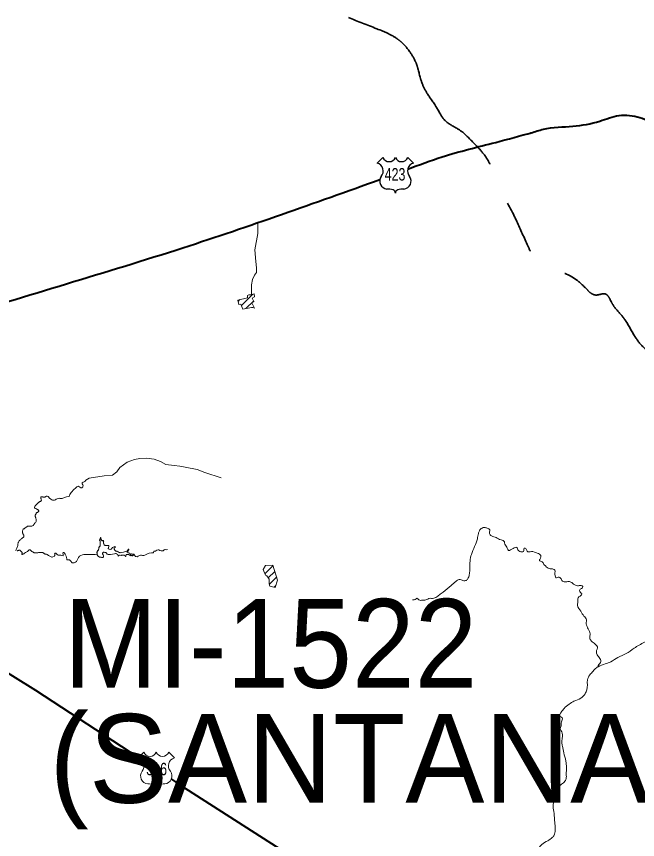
# Model space of a CAD drawing. Extents: x -1643653 to 4543381, y 1624270 to 13878484.
# Drawn here: x 598511 to 602011, y 8914352 to 8918990 of the extents above; entities that cross this region are included whole.
import ezdxf
from ezdxf.enums import TextEntityAlignment as Align

# ---------------------------------------------------------------- set-up
doc = ezdxf.new("R2010")
doc.units = 0
doc.header["$LTSCALE"] = 200
doc.linetypes.add('LONG_DASH_SHORT_DASH', pattern=[9.9, 6, -1.2, 1.5, -1.2])
doc.layers.add('6', color=7, linetype='Continuous', lineweight=13)
doc.layers.add('60', color=7, linetype='Continuous', lineweight=13)

msp = doc.modelspace()

# ---------------------------------------------------------------- linework, layer by layer
at = {"layer": '6', "lineweight": 25}
for p, q in [((600544.7, 8918164.1), (600576.6, 8918196.1)), ((600716.5, 8918196.1), (600748.5, 8918164.1))]:
    msp.add_line(p, q, dxfattribs=at)
at = {"layer": '6'}
for p, q in [((599779.1, 8917360.8), (599843, 8917424.7)), ((599760.1, 8917384.1), (599770.4, 8917394.5)), ((599804.6, 8917343.8), (599848.1, 8917387.3)), ((599850.7, 8917347.5), (599851.7, 8917348.5)), ((599911.6, 8915849.7), (599957.3, 8915895.4)), ((599930.4, 8915826.1), (599967.3, 8915863)), ((599936, 8915789.3), (599977.2, 8915830.5)), ((599963, 8915773.8), (599972, 8915782.8)), ((599197.4, 8914812), (599229.4, 8914844)), ((599369.2, 8914844), (599401.2, 8914812))]:
    msp.add_line(p, q, dxfattribs=at)
for points in [[(599871, 8917832.6), (599871.8, 8917767.7), (599854.5, 8917674.6), (599859.5, 8917608.7), (599864.6, 8917573), (599864.4, 8917548.3), (599853.3, 8917532), (599842.1, 8917507.4), (599836.4, 8917477.3), (599835.9, 8917422.3)], [(599664, 8916389.5), (599573.3, 8916420.2), (599530.2, 8916437.2), (599461.5, 8916451.1), (599431.6, 8916456.9), (599399.5, 8916459.4), (599354, 8916466.4), (599323.1, 8916483.3), (599287.7, 8916495.8), (599244.5, 8916500.6), (599205.7, 8916498.8), (599176.8, 8916494.6), (599135.6, 8916479.4), (599094.3, 8916448.7), (599077.5, 8916423.3), (599051.8, 8916404.7), (599005.2, 8916401.8), (598921.8, 8916388.1), (598911.5, 8916383.7), (598902.3, 8916377.5), (598896.6, 8916370.4)], [(598896.6, 8916370.4), (598896.5, 8916370.3), (598893.5, 8916368.7), (598887.3, 8916366.8), (598882.2, 8916362.8), (598880.8, 8916359.9), (598881.9, 8916356.9), (598884.8, 8916351.1), (598886.9, 8916345), (598886.3, 8916341.8), (598884.8, 8916338.9), (598880.1, 8916334.3), (598877, 8916333.6), (598873.8, 8916334.3), (598868.3, 8916337.8), (598863.6, 8916342.2), (598860.4, 8916342.9), (598857.1, 8916342.3), (598851.2, 8916339.6), (598846.8, 8916334.9), (598841.8, 8916330.9), (598836.5, 8916327.1), (598819.4, 8916307.3), (598815.4, 8916302.1), (598813, 8916296.2), (598811.1, 8916289.8), (598809.4, 8916287.1), (598806.8, 8916285.3), (598793.8, 8916283.8), (598781.7, 8916278.8), (598769.7, 8916273.6), (598763.3, 8916273), (598756.9, 8916274.3)], [(598756.7, 8916274.4), (598751.2, 8916275.1), (598746, 8916273.7), (598736, 8916269.2), (598731.6, 8916266.1), (598726.3, 8916264.3), (598720.8, 8916264.1), (598715.4, 8916265), (598710.1, 8916266.6), (598705.4, 8916269.2), (598697.1, 8916276.4), (598689.5, 8916284.3), (598684.8, 8916287.2), (598682.1, 8916287.3), (598679.5, 8916286.3)], [(599008.9, 8915970.5), (599005.2, 8915971.1), (599001.8, 8915970.8), (598999, 8915968.7), (598996.6, 8915966.3), (598996.6, 8915962.6), (598998.2, 8915958.4), (599000.3, 8915955.5), (599001.3, 8915951.8), (599001.6, 8915948.2), (599001.1, 8915944.2), (599000.3, 8915942.6), (598996.1, 8915942.1), (598992.9, 8915942.1), (598988.2, 8915942.4), (598980.2, 8915944.2), (598973.4, 8915946.6), (598969.4, 8915950.7), (598967.1, 8915956.6), (598965.2, 8915970.8), (598965.5, 8915975.2), (598968.9, 8915978.4), (598971.6, 8915982.3), (598974.5, 8915987), (598975.3, 8915992.3), (598975.3, 8915995.2), (598975.5, 8915998.1), (598976.8, 8916000.4), (598980.5, 8916004.1), (598983.4, 8916008.3), (598983.4, 8916013.8), (598983.2, 8916023.6), (598982.9, 8916029.1), (598982.9, 8916032.5), (598981.6, 8916036.2), (598979, 8916039.9), (598981.8, 8916043.3), (598983.7, 8916049.1), (598985.3, 8916051.4), (598985.5, 8916054.1), (598987.1, 8916053.5), (598987.4, 8916050.1), (598987.7, 8916046.6), (598989.2, 8916043.5), (598993.2, 8916037), (598994.2, 8916034.6), (598996.6, 8916034.9), (598999, 8916036.4), (599001.1, 8916036.7), (599002.9, 8916034.1), (599001.3, 8916030.1), (599001.6, 8916025.9), (599001.6, 8916022), (599003.2, 8916017.2), (599005.3, 8916012.8), (599008.7, 8916010.4), (599011.8, 8916009.8)], [(599084.8, 8915949.4), (599084.9, 8915951), (599083.9, 8915953.7), (599079.6, 8915958), (599076.2, 8915963), (599073.6, 8915964.1), (599070.4, 8915964.2), (599064.2, 8915963), (599040.7, 8915959.1), (599028.6, 8915958.6), (599023.2, 8915961.1), (599019.1, 8915965.5), (599014.9, 8915969.5), (599008.8, 8915970.5), (599002.7, 8915971), (598997.7, 8915967.7), (598996.3, 8915965.3), (598996.7, 8915962.2), (598999.3, 8915956.9), (599001.4, 8915951.3), (599001.3, 8915945.3), (599000.2, 8915942.6), (598997.3, 8915942), (598991.2, 8915942.1), (598979.4, 8915944.4), (598973.7, 8915946.4), (598969.8, 8915950.1), (598967.4, 8915955.4), (598966.2, 8915961.8), (598965.5, 8915968.6), (598965.3, 8915974.9), (598969.6, 8915979.1), (598972.8, 8915984.2), (598975.1, 8915989.6), (598975.3, 8915995.6), (598975.7, 8915998.6), (598977.4, 8916001.1), (598981.7, 8916005.3), (598983.3, 8916007.9), (598983.7, 8916010.8), (598983.3, 8916016.9), (598982.9, 8916028.8), (598982.4, 8916034.8), (598978.9, 8916039.8), (598982.5, 8916044.6), (598983.1, 8916047.6), (598984.6, 8916050.1), (598985.2, 8916053.2), (598985.8, 8916054.1), (598987.3, 8916053.4), (598987.5, 8916047.2), (598993.2, 8916036.7), (598993.7, 8916035.1), (598994.8, 8916034.4), (598997.7, 8916035.6), (599000.4, 8916036.8), (599002.7, 8916035), (599002.3, 8916032.1), (599001.2, 8916029.3), (599001.6, 8916023.2), (599003.1, 8916017.5), (599005.8, 8916012.2), (599008.3, 8916010.6), (599011.3, 8916009.8), (599017.3, 8916009.3), (599029.2, 8916008.2), (599032, 8916006.7), (599032.1, 8916004), (599029.5, 8915998.4), (599028.7, 8915992.5), (599030.6, 8915990.1), (599033.2, 8915988.5), (599038.9, 8915986.9), (599045, 8915987.8), (599047.6, 8915989.5), (599049, 8915992.2), (599049.9, 8915995.1), (599052.1, 8915996.9), (599057.1, 8916000.2), (599062.8, 8916002.2), (599065.4, 8916003.5), (599068.2, 8916003.6), (599068.2, 8916000.4), (599067.4, 8915997.6), (599062.5, 8915994.1), (599062.3, 8915988.1), (599065, 8915982.7), (599069.2, 8915978.6), (599071.7, 8915976.9), (599074.9, 8915976.9), (599077.9, 8915976.9), (599079.8, 8915974.8), (599082.2, 8915973.6), (599085.4, 8915973.6), (599090.5, 8915970.2), (599093, 8915968.8)], [(599093, 8915968.8), (599096, 8915968.4), (599102, 8915968.8), (599113.8, 8915971.1), (599125.2, 8915974.7), (599130.8, 8915973.1), (599134.3, 8915973.4), (599135.2, 8915974), (599134.6, 8915975.3), (599134.3, 8915978.3), (599136.3, 8915980.6), (599138.7, 8915982.3), (599141.3, 8915983.6), (599141.8, 8915985), (599141.2, 8915986.4), (599141.1, 8915987.6), (599142.8, 8915987.7), (599144.3, 8915986.8), (599144.6, 8915985.5), (599142.6, 8915983.1), (599139.9, 8915977.8), (599139.2, 8915971.8), (599139.2, 8915968.8), (599141.3, 8915967), (599147.4, 8915966.3), (599150.5, 8915965.1), (599152.7, 8915963), (599152.8, 8915960), (599154.1, 8915959.1), (599155.8, 8915959.1), (599157.2, 8915961.6), (599159.7, 8915962.2), (599166.6, 8915960.2), (599172.6, 8915960.3), (599175.4, 8915959.6), (599177.1, 8915956.7), (599177, 8915955.3), (599175.6, 8915955.1), (599173.2, 8915956.8), (599167.2, 8915957.4), (599167, 8915955.9), (599168.3, 8915955.1), (599168.7, 8915953.8), (599167.5, 8915952.9), (599165.6, 8915950.8), (599162.7, 8915951.6), (599160.7, 8915953.8), (599159.3, 8915953.6), (599158.3, 8915952.4), (599155.8, 8915950.9), (599153.3, 8915952.5), (599147.8, 8915954.7), (599143.4, 8915958.7), (599137.4, 8915959.2), (599134.3, 8915959.1), (599132, 8915957.4), (599129.5, 8915955.8), (599127.7, 8915953.4), (599127.5, 8915947.2), (599127.1, 8915946.7), (599126.1, 8915947.5), (599123.5, 8915950.7), (599118.3, 8915953.7), (599112.6, 8915955.2), (599106.6, 8915954.9), (599103.8, 8915953.7), (599100.8, 8915953.5), (599094.9, 8915954.2), (599091.9, 8915954.2), (599089.1, 8915953.3), (599087.7, 8915950.6), (599084.9, 8915949.5)], [(599176.8, 8915955.2), (599177.7, 8915952.1), (599179.8, 8915949.5), (599182.3, 8915947.3), (599185.3, 8915946.2), (599191.9, 8915945.7), (599197.9, 8915948.5), (599209.9, 8915953.8), (599212.9, 8915955.1), (599216.1, 8915954.6), (599222.5, 8915953.2), (599228.9, 8915952.1), (599235.1, 8915954.3), (599246.6, 8915960.7), (599258.6, 8915965.9), (599271.5, 8915967.2), (599278, 8915967.5), (599281.5, 8915967.6), (599284.1, 8915969.1), (599286.3, 8915975.3), (599288.3, 8915977.7), (599291.6, 8915977.5), (599294.8, 8915977.3), (599297.7, 8915979), (599303, 8915982.6), (599309.2, 8915984.8), (599312.6, 8915985.5), (599315.2, 8915983.9), (599317.7, 8915981.7), (599320.7, 8915980.5), (599327.2, 8915979.6), (599333.7, 8915979.2), (599336.9, 8915978.5), (599338.4, 8915979), (599339.3, 8915980.4), (599343.9, 8915985), (599346.9, 8915986.2), (599350.2, 8915986.3), (599356.7, 8915984.8), (599363.2, 8915985.6)], [(598679.3, 8915960.3), (598680.9, 8915959.6), (598684.7, 8915957.5), (598691.2, 8915953.3), (598703.5, 8915946.7), (598710, 8915943.5), (598713.4, 8915943.1), (598716.8, 8915944.3), (598723, 8915947.6), (598725.8, 8915949.9), (598727.3, 8915953), (598727.4, 8915960.1), (598726.6, 8915963.4), (598727.6, 8915964.8), (598729.4, 8915965.5), (598732.8, 8915965.5), (598736.1, 8915964.1), (598741.1, 8915959.1), (598743.6, 8915956.6), (598746.7, 8915954.8), (598753.7, 8915954.9), (598760.8, 8915955.2), (598767.5, 8915952.9), (598774, 8915950.1), (598775.1, 8915951.3), (598775, 8915953.1), (598775.4, 8915956.6), (598774.8, 8915960), (598773.3, 8915963.2), (598773.3, 8915966.7), (598776, 8915969), (598779.5, 8915968.9), (598782, 8915966.5), (598785.6, 8915960.4), (598792.2, 8915948), (598795, 8915934.1), (598795.2, 8915930.6), (598796.7, 8915927.7), (598800.2, 8915927.6), (598804.3, 8915928.3), (598807.8, 8915928.6), (598811, 8915927.6), (598816.6, 8915923.1), (598824.8, 8915912), (598825.9, 8915911.7)]]:
    msp.add_lwpolyline(points, dxfattribs=at)
for points in [[(599850.5, 8917427.2), (599834.3, 8917421.8), (599821.6, 8917421.3), (599813.8, 8917417.5), (599813.2, 8917405.3), (599758.2, 8917391.4), (599764.6, 8917366.4), (599775.7, 8917369.7), (599787.1, 8917340.2), (599836, 8917350.3), (599843.2, 8917350.2), (599852.5, 8917346.8), (599837.8, 8917375.8), (599849.5, 8917384.5), (599839.7, 8917403.4), (599853.1, 8917410)], [(599968.6, 8915772.5), (599982.2, 8915814.2), (599956.8, 8915897.3), (599915.6, 8915895.7), (599902.2, 8915874.7), (599914.8, 8915841.3), (599922.6, 8915837.8), (599935.3, 8915818.7), (599934.5, 8915793.9), (599939.4, 8915779.5)]]:
    msp.add_lwpolyline(points, close=True, dxfattribs=at)
at = {"layer": '6', "lineweight": 40}
for points in [[(596588.2, 8916457.2), (598619.5, 8915193.9), (599198.7, 8914813.4)], [(599384.5, 8914691.3), (599431.6, 8914660.4), (600961.1, 8913682.3), (601460.1, 8913331.7), (601690.5, 8912983.4), (601771, 8912890.8), (601830.7, 8912847.9), (601883.5, 8912819.1), (601916.8, 8912809.3)]]:
    msp.add_lwpolyline(points, dxfattribs=at)
at = {"layer": '6', "lineweight": 25}
for centre, radius, start, end in [((600611.6, 8918209.5), 37.4, 200.9593, 339.0407), ((600681.5, 8918209.5), 37.4, 200.9593, 339.0407), ((600532.2, 8918119.7), 46.1, 317.5721, 74.3689), ((600760.9, 8918119.7), 46.1, 105.6277, 222.4279), ((600602.9, 8918062.7), 44.9, 144.7373, 264.6578), ((600690.2, 8918062.7), 44.9, 275.3422, 35.2627), ((600598.5, 8917900), 118, 72.8937, 89.9006), ((600627.7, 8917994.7), 18.9, 357.6934, 72.9296), ((600665.4, 8917994.7), 18.9, 107.0704, 182.3065), ((600694.6, 8917900), 118, 90.0994, 107.1063)]:
    msp.add_arc(centre, radius, start, end, dxfattribs=at)
at = {"layer": '6'}
for centre, radius, start, end in [((599264.3, 8914857.4), 37.4, 200.9593, 339.0407), ((599334.3, 8914857.4), 37.4, 200.9593, 339.0407), ((599185, 8914767.6), 46.1, 317.5721, 74.3689), ((599413.6, 8914767.6), 46.1, 105.6277, 222.4279), ((599255.7, 8914710.6), 44.9, 144.7373, 264.6578), ((599342.9, 8914710.6), 44.9, 275.3422, 35.2627), ((599251.3, 8914547.9), 118, 72.8937, 89.9006), ((599280.4, 8914642.6), 18.9, 357.6934, 72.9296), ((599318.2, 8914642.6), 18.9, 107.0704, 182.3065), ((599347.3, 8914547.9), 118, 90.0994, 107.1063)]:
    msp.add_arc(centre, radius, start, end, dxfattribs=at)
for points in [[(598300.5, 8917392.3), (598315.3, 8917441.1), (598255.3, 8917504.1), (598239.6, 8917592.4), (598271.1, 8917724.9), (598331, 8917860.5), (598362.6, 8917945.7), (598337.3, 8918008.8), (598271.1, 8918059.2), (598264.8, 8918122.3), (598283.7, 8918169.6), (598293.2, 8918216.9), (598258.5, 8918251.6), (598220.6, 8918330.5), (598230.1, 8918494.5), (598230.1, 8918586), (598223.8, 8918652.2), (598198.6, 8918705.8), (598223.8, 8918775.2), (598277.4, 8918895.6), (598337.3, 8919006), (598365.7, 8919135.4), (598368.9, 8919223.8), (598359.4, 8919260.4), (598397.3, 8919298.2), (598463.5, 8919374), (598532.9, 8919493.9), (598564.4, 8919569.6), (598630.7, 8919607.5), (598678, 8919639.1), (598668.5, 8919676.9), (598715.8, 8919736.9), (598775.8, 8919809.5), (598854.6, 8919853.7), (598920.8, 8919907.3)], [(601609.2, 8914720.1), (601610.4, 8914757.2), (601607.5, 8914794.4), (601595.3, 8914840.8), (601588.3, 8914877.4), (601584.2, 8914897.8), (601587.2, 8914923.4), (601583.7, 8914959.4), (601575.5, 8914976.8), (601580.2, 8914990.7), (601580.2, 8915008.2), (601585.4, 8915021.5), (601583.1, 8915041.8), (601574.4, 8915045.9), (601573.2, 8915055.8), (601581.3, 8915069.7), (601597.6, 8915091.2), (601625.5, 8915115), (601652.7, 8915131.2), (601691.6, 8915149.2), (601715.4, 8915173), (601725.8, 8915195.1), (601729.3, 8915251.6), (601734, 8915267.3), (601750.8, 8915290.5), (601770.5, 8915312), (601789.1, 8915326), (601829.1, 8915341.6), (601860.5, 8915353.8), (601900.5, 8915378.2), (601947.5, 8915399.7), (601991.6, 8915429.9), (602050.8, 8915463.6), (602115.8, 8915492.6), (602158.7, 8915505.4), (602314.3, 8915536.7), (602476.2, 8915677.8), (602669.4, 8915813.7), (602862.7, 8915954.7), (603014.1, 8916106.3), (603097.7, 8916148.1), (603186.5, 8916137.6), (603238.7, 8916163.8), (603270, 8916247.4), (603290.9, 8916378), (603348.4, 8916461.6), (603437.2, 8916492.9), (603499.8, 8916524.3), (603536.4, 8916555.7), (603567.7, 8916691.5), (603620, 8916775.1), (603620, 8916874.4), (603661.7, 8916952.8), (603729.6, 8917041.6), (603828.9, 8917146.1)], [(600743.3, 8915702.8), (600758.9, 8915705), (600766.6, 8915711.7), (600778.8, 8915702.8), (600799.9, 8915700.6), (600823.2, 8915703.9), (600834.4, 8915710.6), (600849.9, 8915710.6), (600875.4, 8915716.1), (600894.3, 8915730.6), (600915.4, 8915746.1), (600960.9, 8915783.8), (600986.5, 8915806), (601006.4, 8915817.1), (601027.5, 8915811.6), (601046.4, 8915812.7), (601057.5, 8915826), (601064.2, 8915850.4), (601066.4, 8915878.2), (601067.5, 8915921.5), (601075.3, 8915959.2), (601093, 8916003.7), (601108.6, 8916045.8), (601114.1, 8916076.9), (601119.7, 8916092.5), (601135.2, 8916106.9), (601148.5, 8916111.3), (601164.1, 8916105.8), (601178.5, 8916096.9), (601176.3, 8916075.8), (601188.5, 8916063.6), (601214, 8916053.6), (601241.8, 8916040.3), (601260.7, 8916030.3), (601262.9, 8916015.9), (601270.7, 8916004.8), (601277.3, 8915993.7), (601284, 8915981.4), (601295.1, 8915983.7), (601310.6, 8915992.6), (601330.6, 8915998.1), (601337.3, 8915983.7), (601348.4, 8915975.9), (601368.4, 8915975.9), (601372.8, 8915993.7), (601381.7, 8915992.6), (601388.3, 8915977), (601412.8, 8915974.8), (601446.1, 8915965.9), (601466.1, 8915952.6), (601463.8, 8915938.2), (601458.3, 8915924.8), (601473.8, 8915917.1), (601483.8, 8915902.6), (601497.1, 8915889.3)], [(598825.9, 8915911.7), (598844.6, 8915914.6), (598861.2, 8915942.1), (598891.6, 8915957.8), (598918, 8915957.8), (598966.1, 8915959.7)], [(601497.1, 8915889.3), (601518.2, 8915877.1), (601536, 8915876), (601544.9, 8915870.4), (601544.9, 8915851.6), (601547.1, 8915839.3), (601551.5, 8915826), (601569.3, 8915830.5), (601577.1, 8915824.9), (601588.2, 8915808.3), (601608.2, 8915803.8), (601628.2, 8915806), (601643.7, 8915797.2), (601672.6, 8915781.6), (601693.7, 8915783.8), (601702.5, 8915777.2), (601695.9, 8915766.1), (601687, 8915762.7), (601689.2, 8915745), (601697, 8915738.1), (601687, 8915723.6), (601677, 8915714.7), (601674.8, 8915691.4), (601672.6, 8915671.4), (601691.4, 8915638.1), (601709.2, 8915611.4), (601723.6, 8915590.3), (601721.4, 8915575.9), (601723.6, 8915560.3), (601736.9, 8915531.4), (601743.6, 8915504.8), (601741.4, 8915487), (601750.3, 8915471.5), (601771.4, 8915453.7), (601785.8, 8915431.5), (601780.2, 8915417), (601780.2, 8915402.6), (601790.2, 8915382.6), (601803.6, 8915361.5), (601802.5, 8915350.4), (601793.6, 8915339.3), (601787.4, 8915325.3)], [(601951.6, 8913649.2), (601909.2, 8913648), (601856.4, 8913641), (601817.5, 8913641.6), (601789.7, 8913653.2), (601753.7, 8913667.7), (601736.3, 8913680.5), (601724.7, 8913690.4), (601710.2, 8913710.1), (601691.6, 8913727.6), (601677.7, 8913751.9), (601657.4, 8913769.3), (601649.2, 8913774), (601640.5, 8913788.6), (601634.2, 8913794.4), (601623.7, 8913798.5), (601613.3, 8913814.8), (601605.7, 8913824.6), (601587.7, 8913836.2), (601579.6, 8913844.9), (601569.8, 8913855.4), (601563.4, 8913859.4), (601556.4, 8913852.5), (601546.5, 8913853.7), (601521.6, 8913864.1), (601504.8, 8913871.1), (601467, 8913892.6), (601448.5, 8913905.3), (601431.6, 8913931.4), (601417.7, 8913965.1), (601398.6, 8914039.4), (601388.7, 8914089.4), (601373, 8914140.5), (601363.2, 8914176.6), (601363.2, 8914193.5), (601373.6, 8914215.5), (601395.7, 8914244), (601422.9, 8914268.4), (601443.8, 8914291), (601471.7, 8914323.5), (601504.8, 8914345), (601530.3, 8914363), (601540.7, 8914375.8), (601547.1, 8914406), (601547.1, 8914431.5), (601544.2, 8914448.3), (601540.7, 8914499.4), (601534.9, 8914539.5), (601541.9, 8914580.1), (601544.2, 8914614.4), (601557.6, 8914638.8), (601576.7, 8914659.1), (601598.2, 8914675.9), (601608.6, 8914694.5), (601609.2, 8914720.1)]]:
    msp.add_spline(points, degree=3, dxfattribs=at)
at = {"layer": '6', "linetype": 'LONG_DASH_SHORT_DASH', "lineweight": 35}
msp.add_spline([(600381.6, 8918983.9), (600541.4, 8918921.3), (600673.5, 8918851.8), (600729.1, 8918789.3), (600763.8, 8918726.8), (600791.6, 8918629.5), (600819.4, 8918566.9), (600875, 8918483.6), (600930.6, 8918400.2), (601007, 8918351.5), (601076.5, 8918289), (601146, 8918212.6), (601243.3, 8918011), (601326.7, 8917844.3), (601389.2, 8917705.3), (601458.7, 8917601.1), (601549, 8917559.4), (601625.5, 8917531.6), (601715.8, 8917462.1), (601778.3, 8917420.4), (601827, 8917427.3), (601868.7, 8917371.8), (601924.2, 8917302.3), (602042.4, 8917128.5), (602132.7, 8917059.1), (602195.3, 8916968.7), (602237, 8916871.4), (602293.6, 8916815.3), (602362.3, 8916791.5), (602370.9, 8916763.8), (602382.4, 8916729.4), (602386.2, 8916632), (602375.9, 8916614.3), (602341.3, 8916526), (602362, 8916503.2), (602415.8, 8916437.2), (602443.5, 8916415.3), (602473.2, 8916343.3), (602487.1, 8916183.5), (602501, 8916086.2), (602528.4, 8916025.6), (602570.4, 8915982.6), (602548.4, 8915898.7), (602535.1, 8915867.2), (602486.4, 8915817.5), (602441.6, 8915736.4), (602464.5, 8915679.2), (602557, 8915738.3), (602710.7, 8915862.4), (602741.2, 8915892.9), (602862.4, 8915972.1), (603008.4, 8916103.8), (603086.7, 8916151.5), (603209.8, 8916155.7), (603293.2, 8916155.7)], degree=3, dxfattribs=at)
at = {"layer": '6', "lineweight": 40}
for points in [[(601410.6, 8918334.5), (601480.5, 8918354.8), (601646.5, 8918371.9), (601798.2, 8918400.6), (601906.9, 8918432.1), (602024.2, 8918420.6), (602124.4, 8918386.2), (602247.5, 8918383.4), (602364.8, 8918414.9), (602473.5, 8918412), (602596.6, 8918403.4), (602713.9, 8918400.6), (602825.5, 8918446.4), (602962.9, 8918515.1), (603180.4, 8918558), (603380.7, 8918598.1), (603598.2, 8918666.8), (603804.2, 8918755.6), (603978.8, 8918830), (604145.9, 8918875.8), (604200.3, 8918893), (604251.8, 8918870.1), (604446.4, 8918801.4), (604606.7, 8918732.7), (604769.8, 8918601)], [(600716.1, 8918129.4), (600909.4, 8918199.2), (601211.8, 8918280.7), (601418.4, 8918336.7)], [(596244.3, 8916699.1), (596768.6, 8916837.7), (598135.3, 8917279.9), (599449.7, 8917687.2), (600558.2, 8918071.1)]]:
    msp.add_spline(points, degree=3, dxfattribs=at)
at = {"layer": '6'}
for points in [[(598679.5, 8916286.3), (598678.8, 8916285.7), (598676.5, 8916284.7), (598673.8, 8916283), (598669.9, 8916281.6), (598665.8, 8916281.6), (598661, 8916282.2), (598658.3, 8916283.1), (598654, 8916284.1), (598650, 8916283.7), (598648.7, 8916281.8), (598648, 8916277.7), (598648, 8916275.1), (598649.7, 8916271.8), (598651.9, 8916267.3), (598651.9, 8916263), (598648.3, 8916258.8), (598644, 8916256.1), (598639.5, 8916253.8), (598636.1, 8916251.4), (598631.7, 8916247.3), (598626.6, 8916242.6), (598622.3, 8916238.7), (598618.9, 8916234.5), (598615.1, 8916228.9), (598613.5, 8916224.3), (598612.7, 8916220.8), (598614.4, 8916218.5), (598621, 8916217.1), (598626.8, 8916214.2), (598633, 8916210.8), (598635.1, 8916207.7), (598637.2, 8916203.7), (598636.7, 8916200), (598632.4, 8916196.2), (598628.8, 8916194.5), (598625.1, 8916193.8), (598621.6, 8916187.9), (598619, 8916182.7), (598617.6, 8916180), (598616.8, 8916177.7), (598616.8, 8916174.6), (598617.8, 8916170.6), (598619.8, 8916163.9), (598621.8, 8916158), (598623.8, 8916151), (598622.9, 8916145.1), (598616.7, 8916137.4), (598611.9, 8916132.6), (598609.7, 8916127.3), (598605.8, 8916120.6), (598598.2, 8916118), (598588.6, 8916117.2), (598581.9, 8916118.5), (598576.4, 8916118.5), (598572.5, 8916116.3), (598566.9, 8916112), (598560.8, 8916108.9), (598556.5, 8916105.6), (598551.7, 8916102.2), (598547.7, 8916098.3), (598545.4, 8916092.1), (598545.5, 8916088.6), (598545.5, 8916082.7), (598546.1, 8916078.2), (598549, 8916072.8), (598552.4, 8916067.2), (598554.1, 8916062.7), (598552.4, 8916057.7), (598549.3, 8916053.8), (598543, 8916049.8), (598536.7, 8916044.7), (598530.5, 8916038.6), (598524.2, 8916031), (598521.6, 8916025.1), (598519.9, 8916018.9), (598518.5, 8916009.1), (598515.9, 8915999), (598512, 8915990.6), (598510.7, 8915987.1), (598507, 8915979.5)], [(598515.9, 8915979.5), (598516.1, 8915979.6), (598518.1, 8915980.2), (598522.2, 8915981.3), (598526.3, 8915982.8), (598531.6, 8915982.8), (598534.6, 8915979.2), (598536.3, 8915976.7), (598537.6, 8915975.5)], [(598537.6, 8915975.5), (598538.8, 8915974.2), (598541.8, 8915971.8), (598544.6, 8915968.8), (598543.2, 8915964.3), (598541, 8915961), (598541.6, 8915958.6), (598545.1, 8915959.2), (598551.8, 8915962.7), (598562.2, 8915968), (598577.8, 8915978.9), (598582.3, 8915982.7), (598585.4, 8915984.9), (598588.7, 8915984.2), (598592.3, 8915981.1), (598595.8, 8915977.2), (598600.7, 8915975), (598605.8, 8915971.6), (598609.7, 8915968.4), (598613.4, 8915967.2), (598617.7, 8915966.8), (598623, 8915967.3), (598628.1, 8915968.3), (598636.4, 8915968.8), (598645.4, 8915970), (598654.4, 8915969.8), (598659.8, 8915969.2), (598663.5, 8915966.9), (598667.4, 8915963), (598671, 8915961), (598675, 8915960.6), (598677.9, 8915960.6), (598679.3, 8915960.3)]]:
    msp.add_open_spline(points, degree=3, dxfattribs=at)
at = {"layer": '60', "lineweight": 25}
msp.add_spline([(814781, 9009175.5), (814787.2, 9009173.4), (814796.9, 9009173.4), (814799.4, 9009172.4), (814805.1, 9009174.5), (814805.6, 9009176.5), (814811.7, 9009179.5), (814811.7, 9009179.5), (814801.5, 9009181), (814790.7, 9009181.5), (814784.1, 9009183.1), (814777.4, 9009185.1), (814778.4, 9009175.5)], degree=3, dxfattribs=at)

# ---------------------------------------------------------------- texts
at = {"layer": '6', "width": 0.75}
for s, p in [('423', (600644.5, 8918065.8)), ('316', (599301.3, 8914714.4))]:
    msp.add_text(s, height=70, dxfattribs=at).set_placement(p, align=Align.CENTER)
at = {"layer": '6', "width": 0.95}
msp.add_text('MI-1522', height=500, dxfattribs=at).set_placement((598778.2, 8915207.6))
at = {"layer": '6'}
msp.add_text('(SANTANA DO IPANEMA)', height=500, dxfattribs=at).set_placement((598696.7, 8914559.1))

doc.saveas('drawing.dxf')
